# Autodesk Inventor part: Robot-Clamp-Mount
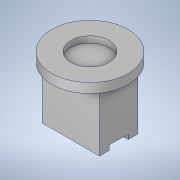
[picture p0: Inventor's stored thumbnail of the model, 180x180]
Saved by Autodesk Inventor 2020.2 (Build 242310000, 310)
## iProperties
Created: 2018-07
Part Number: Robot-Clamp-Mount
Material: Aluminum 6061
Description: 123456
Document SubType Name: Modeling
Designer: Power User
Mass: 486.263 g
Surface Area: 257.832 cm^2
Volume: 180.097 cm^3
Density: 2.7 g/cm^3
Appearance: Aluminum - Flat
Title: GEAR
Author: Power User
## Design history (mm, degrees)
sketch "Sketch6"
  geometry: L1 (60, 20)-(0, 20); L2 (0, -20)-(60, -20); L3 (60, -20)-(60, 20); L4 (0, 10)-(5, 10); L5 (5, 10)-(5, -10); L6 (5, -10)-(0, -10); L7 (0, 20)-(0, 10); L8 (0, -10)-(0, -20); 4 further points
  constraints: 16 end point, 7 perpendicular, 3 parallel, 2 coincident, 2 horizontal alignment, 2 midpoint, 2 vertical alignment, 1 horizontal
  dimensions: "d44" = 40 distance between parallel lines of L2 L1; "d45" = 20 distance of L4.end L5.end; "d46" = 5 distance from line of L5 point (0, 0); "d47" = 60 distance from line of point (0, 0) L3
extrude "Extrusion5" new body sketch "Sketch6" stored distance "d48" = 60; taper "d49" = 0 deg
sketch "Sketch7"
  geometry: C1 r 40 at (30, 20); 1 further point
  constraints: 1 centre point, 1 coincident
  dimensions: "d50" = 80 diameter of C1
extrude "Extrusion6" join sketch "Sketch7" distance "d51" = 10; taper "d52" = 0 deg
sketch "Sketch8"
  geometry: C1 r 40 at (0, 0) reference; 2 further points
  constraints: 1 coincident
hole "Hole2" sketch "Sketch8" at (0, 0) diameter "d53" = 40; stored, may be unused: countersink angle "d57" = 90 deg, drill point angle "d59" = 0 deg; dims "d54" = 6, "d55" = 4, "d56" = 2, "d58" = 6.5
body "Solid2"
